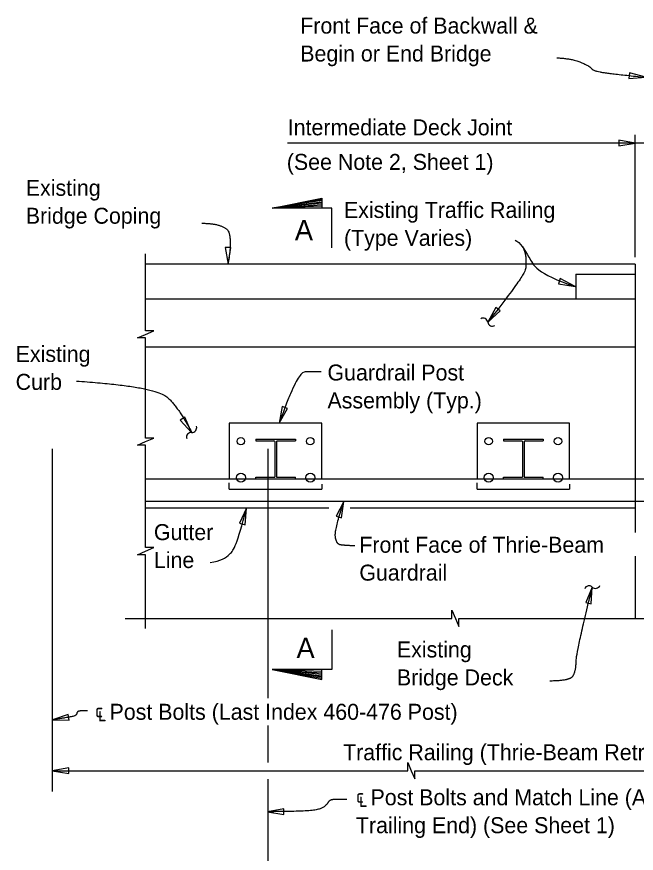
# Model space of a CAD drawing. Extents: x 21587 to 21659.1, y 56116.2 to 56157.3.
# Drawn here: x 21605.69 to 21613.5, y 56142.29 to 56152.84 of the extents above; entities that cross this region are included whole.
import ezdxf

# ---------------------------------------------------------------- set-up
doc = ezdxf.new("R2010")
doc.units = 0
for name, color, linetype in [('AdhocPoint_dp', 7, 'Continuous'), ('Border', 7, 'Continuous'), ('PlotBorder_dp', 7, 'Continuous'), ('SheetBorder_dp', 7, 'Continuous'), ('TextMisc', 7, 'Continuous')]:
    doc.layers.add(name, color=color, linetype=linetype)

msp = doc.modelspace()

# ---------------------------------------------------------------- linework, layer by layer
at = {"layer": 'AdhocPoint_dp'}
for p, q in [((21613.488, 56149.72), (21607.312, 56149.72)), ((21613.488, 56149.722), (21613.488, 56146.335)), ((21612.738, 56149.595), (21613.488, 56149.595)), ((21607.312, 56149.282), (21613.488, 56149.282)), ((21607.312, 56148.678), (21613.488, 56148.678)), ((21607.312, 56146.648), (21609.624, 56146.648)), ((21609.894, 56146.648), (21613.488, 56146.648)), ((21613.488, 56146.038), (21613.488, 56145.254))]:
    msp.add_line(p, q, dxfattribs=at)
msp.add_lwpolyline([(21612.738, 56149.595), (21612.738, 56149.282)], dxfattribs=at)
at = {"layer": 'Border'}
for p, q in [((21608.702, 56147.514), (21609.202, 56147.514)), ((21608.702, 56147.514), (21608.702, 56147.493)), ((21608.702, 56147.493), (21608.931, 56147.493)), ((21608.941, 56147.483), (21608.941, 56147.035)), ((21608.962, 56147.483), (21608.962, 56147.035)), ((21608.973, 56147.493), (21609.202, 56147.493)), ((21609.202, 56147.514), (21609.202, 56147.493)), ((21611.827, 56147.514), (21612.327, 56147.514)), ((21611.827, 56147.514), (21611.827, 56147.493)), ((21611.827, 56147.493), (21612.056, 56147.493)), ((21612.066, 56147.483), (21612.066, 56147.035)), ((21612.087, 56147.483), (21612.087, 56147.035)), ((21612.098, 56147.493), (21612.327, 56147.493)), ((21612.327, 56147.514), (21612.327, 56147.493)), ((21607.312, 56147.012), (21619.379, 56147.012)), ((21608.702, 56147.035), (21608.941, 56147.035)), ((21608.702, 56147.014), (21608.702, 56147.035)), ((21608.702, 56147.014), (21609.202, 56147.014)), ((21608.962, 56147.035), (21609.202, 56147.035)), ((21609.202, 56147.014), (21609.202, 56147.035)), ((21611.827, 56147.035), (21612.066, 56147.035)), ((21611.827, 56147.014), (21611.827, 56147.035)), ((21611.827, 56147.014), (21612.327, 56147.014)), ((21612.087, 56147.035), (21612.327, 56147.035)), ((21612.327, 56147.014), (21612.327, 56147.035)), ((21607.312, 56146.732), (21619.379, 56146.732))]:
    msp.add_line(p, q, dxfattribs=at)
for points in [[(21609.535, 56147.012), (21609.535, 56147.717), (21608.368, 56147.717), (21608.368, 56147.012)], [(21612.66, 56147.012), (21612.66, 56147.717), (21611.493, 56147.717), (21611.493, 56147.012)], [(21608.368, 56146.884), (21608.368, 56146.962)], [(21609.535, 56146.946), (21609.535, 56146.884)], [(21611.493, 56146.884), (21611.493, 56146.962)], [(21612.66, 56146.946), (21612.66, 56146.884)]]:
    msp.add_lwpolyline(points, dxfattribs=at)
for centre, radius in [((21608.514, 56147.488), 0.0469), ((21609.389, 56147.488), 0.0469), ((21611.639, 56147.488), 0.0469), ((21612.514, 56147.488), 0.0469), ((21608.514, 56147.03), 0.0573), ((21609.389, 56147.03), 0.0573), ((21611.639, 56147.03), 0.0573), ((21612.514, 56147.03), 0.0573)]:
    msp.add_circle(centre, radius, dxfattribs=at)
for centre, start, end in [((21608.931, 56147.483), 0, 90), ((21608.973, 56147.483), 90, 180), ((21612.056, 56147.483), 0, 90), ((21612.098, 56147.483), 90, 180)]:
    msp.add_arc(centre, 0.0104, start, end, dxfattribs=at)
at = {"layer": 'PlotBorder_dp'}
for p, q in [((21613.488, 56149.808), (21613.488, 56151.352)), ((21613.996, 56151.248), (21609.103, 56151.248)), ((21608.91, 56150.429), (21609.535, 56150.539)), ((21609.535, 56150.526), (21608.91, 56150.429)), ((21608.91, 56150.429), (21609.535, 56150.509)), ((21609.535, 56150.491), (21608.91, 56150.429)), ((21608.91, 56150.429), (21609.535, 56150.473)), ((21609.535, 56150.453), (21608.91, 56150.429)), ((21608.858, 56144.246), (21608.858, 56147.393)), ((21609.535, 56144.586), (21608.91, 56144.609)), ((21608.91, 56144.609), (21609.535, 56144.566)), ((21609.535, 56144.547), (21608.91, 56144.609)), ((21608.91, 56144.609), (21609.535, 56144.529)), ((21609.535, 56144.512), (21608.91, 56144.609)), ((21608.91, 56144.609), (21609.535, 56144.499)), ((21608.858, 56143.438), (21608.858, 56143.901)), ((21608.858, 56135.158), (21608.858, 56143.226))]:
    msp.add_line(p, q, dxfattribs=at)
for points in [[(21613.62, 56152.078), (21613.416, 56152.134), (21613.409, 56152.064)], [(21613.488, 56151.248), (21613.28, 56151.283), (21613.28, 56151.212)], [(21608.352, 56149.721), (21608.388, 56149.93), (21608.317, 56149.93)], [(21612.73, 56149.441), (21612.543, 56149.539), (21612.521, 56149.472)], [(21611.628, 56148.989), (21611.785, 56149.131), (21611.73, 56149.175)], [(21608.998, 56147.717), (21609.101, 56147.902), (21609.034, 56147.925)], [(21607.893, 56147.6), (21607.806, 56147.793), (21607.748, 56147.754)], [(21609.813, 56146.73), (21609.714, 56146.543), (21609.782, 56146.521)], [(21608.584, 56146.646), (21608.498, 56146.453), (21608.566, 56146.435)], [(21612.947, 56145.649), (21612.863, 56145.455), (21612.931, 56145.438)], [(21606.137, 56143.974), (21606.348, 56143.971), (21606.337, 56144.041)], [(21606.135, 56143.332), (21606.343, 56143.297), (21606.343, 56143.368)], [(21608.848, 56142.816), (21609.056, 56142.781), (21609.056, 56142.851)]]:
    msp.add_lwpolyline(points, close=True, dxfattribs=at)
for points in [[(21609.66, 56149.929), (21609.66, 56150.429), (21608.91, 56150.429), (21609.535, 56150.554), (21609.535, 56150.429)], [(21607.312, 56148.322), (21607.312, 56148.791), (21607.208, 56148.791), (21607.312, 56148.836), (21607.415, 56148.881), (21607.312, 56148.881), (21607.312, 56149.85)], [(21607.312, 56146.575), (21607.312, 56147.438), (21607.208, 56147.438), (21607.312, 56147.483), (21607.415, 56147.528), (21607.312, 56147.528), (21607.312, 56148.322)], [(21607.312, 56145.128), (21607.312, 56146.056), (21607.208, 56146.056), (21607.312, 56146.101), (21607.415, 56146.146), (21607.312, 56146.146), (21607.312, 56147.019)], [(21607.053, 56145.254), (21611.175, 56145.254), (21611.175, 56145.357), (21611.22, 56145.254), (21611.265, 56145.15), (21611.265, 56145.254), (21613.496, 56145.254)], [(21613.496, 56145.254), (21617.776, 56145.254), (21617.776, 56145.357), (21617.821, 56145.254), (21617.866, 56145.15), (21617.866, 56145.254), (21620.131, 56145.254)], [(21609.66, 56145.109), (21609.66, 56144.609), (21608.91, 56144.609), (21609.535, 56144.484), (21609.535, 56144.609)], [(21606.135, 56143.332), (21610.618, 56143.332), (21610.618, 56143.436), (21610.663, 56143.332), (21610.708, 56143.229), (21610.708, 56143.332), (21626.014, 56143.332)]]:
    msp.add_lwpolyline(points, dxfattribs=at)
for centre, start, end in [((21611.569, 56148.981), 8.6098, 120.3371), ((21611.687, 56148.999), 188.6098, 300.3371), ((21607.897, 56147.659), 265.5858, 17.313), ((21607.888, 56147.54), 85.5858, 197.313), ((21612.906, 56145.605), 47.1839, 158.9112), ((21612.987, 56145.692), 227.1839, 338.9112)]:
    msp.add_arc(centre, 0.0596, start, end, dxfattribs=at)
for points, degree in [([(21612.498, 56152.323), (21612.683, 56152.316), (21612.921, 56152.217), (21612.954, 56152.158), (21613.224, 56152.118), (21613.62, 56152.078)], 2), ([(21608.02, 56150.237), (21608.232, 56150.237), (21608.418, 56150.106), (21608.352, 56149.721)], 2), ([(21611.975, 56150.022), (21612.031, 56149.999), (21612.159, 56149.821), (21612.239, 56149.6), (21612.73, 56149.441)], 3), ([(21612.069, 56149.943), (21612.108, 56149.846), (21612.108, 56149.749), (21612.108, 56149.595), (21611.628, 56148.989)], 2), ([(21609.527, 56148.362), (21609.41, 56148.362), (21609.227, 56148.362), (21608.998, 56147.717)], 2), ([(21606.44, 56148.247), (21607.434, 56148.18), (21607.731, 56147.911), (21607.893, 56147.6)], 2), ([(21609.951, 56146.169), (21609.82, 56146.172), (21609.717, 56146.192), (21609.694, 56146.369), (21609.813, 56146.73)], 2), ([(21608.125, 56145.959), (21608.258, 56145.975), (21608.39, 56146.057), (21608.464, 56146.177), (21608.584, 56146.646)], 3), ([(21612.41, 56144.468), (21612.665, 56144.468), (21612.742, 56144.588), (21612.742, 56144.821), (21612.947, 56145.649)], 2), ([(21606.578, 56144.089), (21606.513, 56144.089), (21606.449, 56144.082), (21606.439, 56144.025), (21606.313, 56144.001), (21606.137, 56143.974)], 2), ([(21609.851, 56142.968), (21609.731, 56142.968), (21609.632, 56142.968), (21609.59, 56142.887), (21609.456, 56142.827), (21609.01, 56142.816), (21608.848, 56142.816)], 2)]:
    msp.add_open_spline(points, degree=degree, dxfattribs=at)
at = {"layer": 'TextMisc'}
msp.add_line((21606.135, 56147.393), (21606.135, 56143.07), dxfattribs=at)
for points in [[(21608.368, 56146.884), (21609.535, 56146.884)], [(21611.493, 56146.884), (21612.66, 56146.884)]]:
    msp.add_lwpolyline(points, dxfattribs=at)

# ---------------------------------------------------------------- texts
at = {"layer": 'PlotBorder_dp'}
for s, p in [('Front Face of Backwall &', (21609.263, 56152.629)), ('Begin or End Bridge', (21609.263, 56152.277)), ('Existing ', (21605.801, 56150.583)), ('Existing Traffic Railing', (21609.814, 56150.304)), ('Bridge Coping ', (21605.801, 56150.231)), ('(Type Varies)', (21609.814, 56149.952)), ('Existing ', (21605.673, 56148.488)), ('Guardrail Post ', (21609.606, 56148.254)), ('Curb', (21605.673, 56148.136)), ('Assembly (Typ.)', (21609.606, 56147.902)), ('Gutter ', (21607.417, 56146.241)), ('Front Face of Thrie-Beam ', (21610.008, 56146.082)), ('Line', (21607.417, 56145.889)), ('Guardrail', (21610.008, 56145.73)), ('Existing ', (21610.482, 56144.761)), ('Bridge Deck', (21610.482, 56144.409)), ('℄ Post Bolts and Match Line (Approach or ', (21609.965, 56142.897)), ('Trailing End) (See Sheet 1)', (21609.965, 56142.545))]:
    msp.add_text(s, height=0.2016, dxfattribs=at).set_placement(p)
at = {"layer": 'SheetBorder_dp'}
for s, height, p in [('Intermediate Deck Joint', 0.2016, (21609.105, 56151.346)), ('(See Note 2, Sheet 1)', 0.2016, (21609.093, 56150.91)), ('A', 0.256, (21609.195, 56150.023)), ('A', 0.256, (21609.216, 56144.754)), ('℄ Post Bolts (Last Index 460-476 Post)', 0.2016, (21606.673, 56143.975)), ('Traffic Railing (Thrie-Beam Retrofit) Limits of Payment', 0.2016, (21609.803, 56143.465))]:
    msp.add_text(s, height=height, dxfattribs=at).set_placement(p)

doc.saveas('drawing.dxf')
